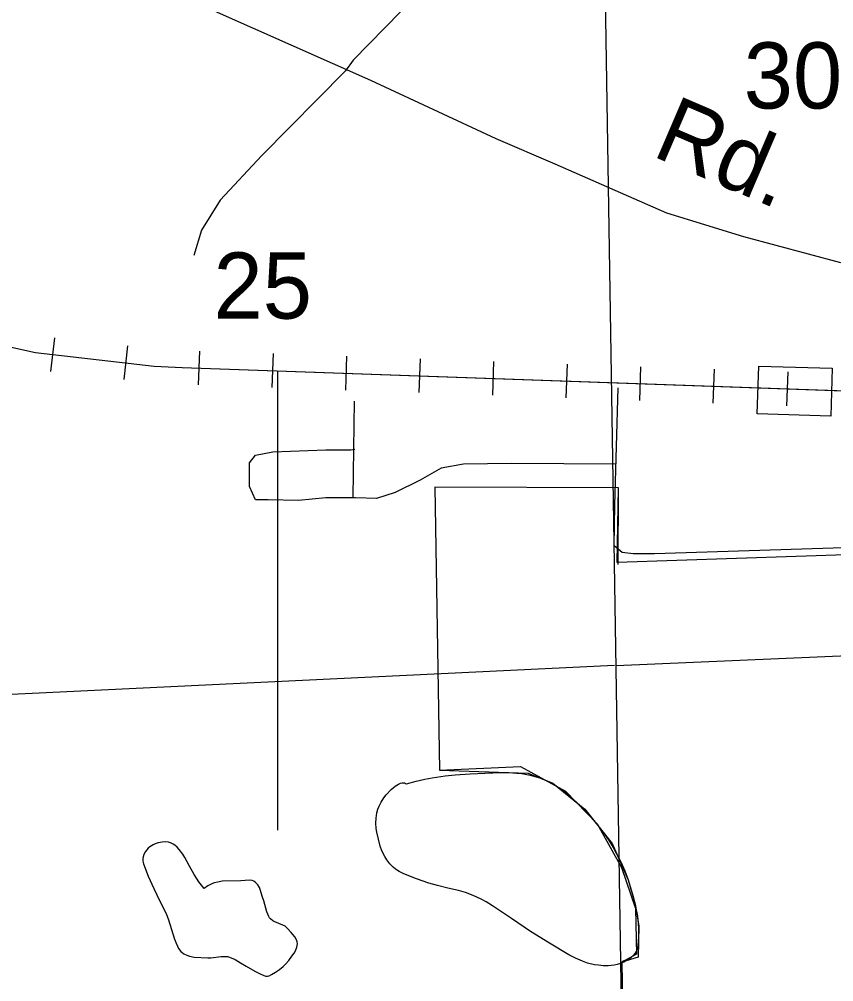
# Model space of a CAD drawing. Extents: x 2480962 to 2688785, y 277103 to 599240.
# Drawn here: x 2545675 to 2551211, y 436042 to 442588 of the extents above; entities that cross this region are included whole.
import ezdxf

# ---------------------------------------------------------------- set-up
doc = ezdxf.new("R2010")
doc.units = 0
for name, color, linetype in [('Cities Incorporated Area', 7, 'Continuous'), ('County Roads Related Text', 7, 'Continuous'), ('County Routes Highway Center Lines', 7, 'Continuous'), ('Lakes and Ponds', 7, 'Continuous'), ('Local Roads Paved', 7, 'Continuous'), ('Railroad Stations', 7, 'Continuous'), ('Railroads', 7, 'Continuous'), ('Section Lines', 7, 'Continuous'), ('Section Numbers', 7, 'Continuous'), ('Swamps', 7, 'Continuous'), ('Township and Range lines', 7, 'Continuous')]:
    doc.layers.add(name, color=color, linetype=linetype)

msp = doc.modelspace()

# ---------------------------------------------------------------- linework, layer by layer
at = {"layer": 'Cities Incorporated Area'}
for p, q in [((2549747.207, 439399.968), (2548499.333, 439406.541)), ((2548499.333, 439406.541), (2548532.218, 437481.839)), ((2549738.264, 438892.674), (2549747.207, 439399.968)), ((2551810.07, 438964.296), (2549738.264, 438892.674)), ((2548532.218, 437481.839), (2549133.672, 437461.643)), ((2549133.672, 437461.643), (2549300.935, 437392.86)), ((2549300.935, 437392.86), (2549519.357, 437216.601)), ((2549519.357, 437216.601), (2549704.592, 436982.806)), ((2549704.592, 436982.806), (2549813.023, 436736.093)), ((2549813.023, 436736.093), (2549861.036, 436569.212)), ((2549861.036, 436569.212), (2549886.56, 436423.341)), ((2549886.56, 436423.341), (2549882.444, 436209.022)), ((2549882.444, 436209.022), (2549769.717, 436175.05)), ((2549769.717, 436175.05), (2549808.561, 434297.514))]:
    msp.add_line(p, q, dxfattribs=at)
at = {"layer": 'County Routes Highway Center Lines'}
msp.add_lwpolyline([(2551260.127, 440930.131), (2550599.271, 441108.275), (2550076.332, 441269.179), (2549317.785, 441602.48), (2548915.524, 441774.878), (2548065.031, 442171.391), (2546720.333, 442769.035)], dxfattribs=at)
at = {"layer": 'Lakes and Ponds'}
for points in [[(2548306.504, 437387.504), (2548372.6, 437406.235), (2548430.599, 437419.65), (2548481.468, 437429.356), (2548570.738, 437442.402), (2548637.887, 437449.435), (2548738.893, 437456.647), (2548840.203, 437461.199), (2548948.549, 437464.432), (2549002.72, 437464.068), (2549056.815, 437461.122), (2549089.785, 437457.551), (2549146.678, 437447.344), (2549188.625, 437436.126), (2549219.65, 437425.565), (2549265.448, 437406.053), (2549310.304, 437381.87), (2549341.57, 437362.054), (2549392.373, 437325.023), (2549427.861, 437295.345), (2549478.191, 437247.894), (2549526.671, 437197.082), (2549567.808, 437151.396), (2549626.102, 437081.415), (2549653.511, 437044.963), (2549679.634, 437007.041), (2549711.193, 436956.1), (2549732.935, 436917.236), (2549762.914, 436857.577), (2549790.304, 436795.904), (2549813.023, 436736.093), (2549827.632, 436690.788), (2549846.762, 436622.234), (2549863.95, 436553.116), (2549876.504, 436488.065), (2549882.081, 436438.485), (2549884.128, 436401.08), (2549883.804, 436344.957), (2549879.452, 436289.239), (2549874.508, 436265.581), (2549867.853, 436248.623), (2549861.145, 436236.539), (2549848.235, 436219.716), (2549831.793, 436204.817), (2549807.634, 436188.584), (2549784.063, 436176.208), (2549761.269, 436166.978), (2549739.383, 436160.304), (2549718.487, 436155.705), (2549678.57, 436151.124), (2549643.161, 436151.106), (2549612.065, 436153.865), (2549584.941, 436158.211), (2549538.098, 436169.683), (2549503.867, 436181.095), (2549454.723, 436201.896), (2549409.165, 436226.077), (2549278.986, 436303.504), (2549150.497, 436384.492), (2549021.557, 436472.073), (2548891.849, 436558.739), (2548847.668, 436585.238), (2548813.639, 436603.442), (2548761.182, 436627.852), (2548707.055, 436648.521), (2548659.978, 436662.33), (2548588.333, 436678.67), (2548516.923, 436696.086), (2548459.426, 436713.352), (2548374.277, 436742.135), (2548289.85, 436775.328), (2548256.286, 436792.269), (2548233.084, 436807.81), (2548216.799, 436821.144), (2548194.179, 436843.976), (2548173.744, 436870.363), (2548159.528, 436893.035), (2548139.802, 436933.468), (2548128.497, 436964.417), (2548115.527, 437011.819), (2548105.312, 437060.375), (2548101.485, 437084.024), (2548098.803, 437119.776), (2548100.154, 437155.371), (2548105.891, 437190.992), (2548113.204, 437216.869), (2548120.542, 437235.954), (2548134.77, 437264.292), (2548153.166, 437292.565), (2548169.558, 437313.66), (2548203.409, 437349.97), (2548231.007, 437372.988), (2548251.768, 437385.802), (2548266.877, 437392.034), (2548277.738, 437394.438), (2548292.96, 437393.84), (2548299.97, 437391.438), (2548306.504, 437387.504)], [(2546931.936, 436675.539), (2546896.054, 436722.083), (2546863.381, 436770.558), (2546831.455, 436828.316), (2546800.134, 436886.683), (2546785.92, 436909.533), (2546762.007, 436941.433), (2546747.842, 436956.516), (2546731.565, 436971.147), (2546721.91, 436978.078), (2546703.798, 436986.746), (2546689.58, 436990.689), (2546667.998, 436993.147), (2546647.061, 436992.287), (2546619.374, 436987.542), (2546599.016, 436981.116), (2546584.058, 436974.206), (2546562.243, 436959.769), (2546551.662, 436950.444), (2546541.328, 436939.55), (2546532.362, 436927.943), (2546521.31, 436907.056), (2546516.701, 436891.165), (2546515.205, 436879.26), (2546515.947, 436861.638), (2546520.07, 436844.564), (2546551.691, 436759.703), (2546588.529, 436675.661), (2546631.141, 436591.114), (2546672.838, 436506.753), (2546689.444, 436464.212), (2546709.299, 436398.358), (2546730.725, 436332.577), (2546741.338, 436304.408), (2546750.155, 436283.682), (2546758.07, 436268.913), (2546773.268, 436248.836), (2546782.83, 436240.047), (2546793.991, 436232.284), (2546814.038, 436222.161), (2546831.727, 436215.957), (2546862.955, 436209.742), (2546957.736, 436205.839), (2546977.613, 436205.687), (2547047.952, 436213.509), (2547065.382, 436214.498), (2547091.139, 436212.878), (2547103.782, 436210.139), (2547116.231, 436205.782), (2547142.587, 436192.771), (2547179.502, 436170.226), (2547216.536, 436147.694), (2547277.106, 436114.208), (2547307.511, 436098.448), (2547337.966, 436084.323), (2547350.806, 436080.95), (2547362.286, 436081.055), (2547372.467, 436083.147), (2547390.457, 436090.439), (2547417.42, 436107.197), (2547443.685, 436126.504), (2547468.842, 436146.89), (2547485.091, 436162.563), (2547507.043, 436187.728), (2547528.334, 436216.19), (2547542.521, 436236.99), (2547551.996, 436252.99), (2547562.316, 436277.087), (2547564.951, 436288.97), (2547565.428, 436300.616), (2547563.081, 436314.469), (2547558.838, 436326.436), (2547547.408, 436347.032), (2547523.719, 436377.102), (2547496.885, 436406.189), (2547481.842, 436419.079), (2547467.035, 436427.821), (2547411.765, 436450.65), (2547399.111, 436456.99), (2547382.59, 436468.971), (2547375.792, 436476.524), (2547370.192, 436485.396), (2547356.996, 436517.372), (2547343.196, 436567.506), (2547336.406, 436592.667), (2547328.1, 436617.347), (2547312.215, 436669.425), (2547307.222, 436682.086), (2547296.655, 436700.41), (2547289.465, 436709.18), (2547280.683, 436717.634), (2547268.766, 436725.855), (2547258.05, 436730.377), (2547238.826, 436733.607), (2547180.316, 436728.226), (2547054.898, 436725.216), (2547023.801, 436720.352), (2547000.61, 436714.025), (2546983.304, 436707.41), (2546957.509, 436693.942), (2546931.936, 436675.539)]]:
    msp.add_lwpolyline(points, dxfattribs=at)
at = {"layer": 'Local Roads Paved'}
msp.add_line((2547950.434, 439989.519), (2547941.251, 439337.571), dxfattribs=at)
for points in [[(2553849.789, 443531.353), (2553552.551, 443339.8), (2552944.863, 442930.271), (2552607.993, 442732.112), (2552224.886, 442613.217), (2551960.674, 442593.401), (2551788.936, 442593.401), (2551399.224, 442626.428), (2550884.01, 442745.323), (2550269.718, 442890.64), (2549675.241, 443029.351), (2549378.003, 443029.351), (2549014.711, 442976.508), (2548631.604, 442851.008), (2548268.313, 442639.638), (2547944.653, 442309.373), (2547891.811, 442236.715), (2547323.755, 441662.054), (2547039.727, 441358.211), (2546914.227, 441153.446), (2546861.384, 440981.709)], [(2551279.038, 438993.233), (2549993.508, 438951.912), (2549846.59, 438951.912), (2549773.132, 438961.095), (2549718.037, 439007.006), (2549722.629, 439282.477), (2549745.585, 440081.342)], [(2549731.811, 439562.539), (2549020.178, 439567.13), (2548694.205, 439562.539), (2548542.696, 439534.992), (2548400.369, 439452.351), (2548230.496, 439369.709), (2548101.943, 439328.389), (2547959.616, 439332.98), (2547757.604, 439332.98), (2547573.957, 439314.615), (2547367.354, 439319.206), (2547280.122, 439319.206), (2547238.801, 439411.03), (2547238.801, 439571.721), (2547280.122, 439622.224), (2547399.492, 439645.18), (2547757.604, 439658.954), (2547927.478, 439658.954), (2547955.025, 439663.545)]]:
    msp.add_lwpolyline(points, dxfattribs=at)
at = {"layer": 'Railroad Stations'}
msp.add_lwpolyline([(2550700.841, 440228.646), (2551200.629, 440214.108), (2551191.179, 439889.245), (2550691.391, 439903.784)], close=True, dxfattribs=at)
at = {"layer": 'Railroads'}
for p, q in [((2545913.627, 440421.644), (2545887.875, 440193.09)), ((2545913.627, 440421.644), (2545887.875, 440193.09)), ((2546410.483, 440365.661), (2546384.731, 440137.108)), ((2546410.483, 440365.661), (2546384.731, 440137.108)), ((2546900.162, 440331.316), (2546892.018, 440101.461)), ((2546900.162, 440331.316), (2546892.018, 440101.461)), ((2547399.849, 440313.61), (2547391.704, 440083.755)), ((2547399.849, 440313.61), (2547391.704, 440083.755)), ((2547899.535, 440295.904), (2547891.39, 440066.049)), ((2547899.535, 440295.904), (2547891.39, 440066.049)), ((2548399.222, 440278.198), (2548391.077, 440048.343)), ((2548399.222, 440278.198), (2548391.077, 440048.343)), ((2548898.908, 440260.492), (2548890.763, 440030.636)), ((2548898.908, 440260.492), (2548890.763, 440030.636)), ((2546781.298, 440220.456), (2557380.702, 439844.874)), ((2549398.594, 440242.786), (2549390.45, 440012.93)), ((2549398.594, 440242.786), (2549390.45, 440012.93)), ((2549898.281, 440225.08), (2549890.136, 439995.224)), ((2549898.281, 440225.08), (2549890.136, 439995.224)), ((2550397.967, 440207.374), (2550389.822, 439977.518)), ((2550397.967, 440207.374), (2550389.822, 439977.518)), ((2550897.654, 440189.668), (2550889.509, 439959.812)), ((2550897.654, 440189.668), (2550889.509, 439959.812))]:
    msp.add_line(p, q, dxfattribs=at)
for points in [[(2504457.222, 450568.165), (2520855.254, 448452.084), (2521247.687, 448380.391), (2521630.476, 448268.069), (2521999.426, 448116.348), (2522298.814, 447957.824), (2522298.813, 447957.824), (2525353.968, 446161.924), (2526001.076, 445825.806), (2526679.773, 445559.173), (2527030.858, 445452.248), (2544991.828, 440495.215), (2545784.966, 440320.413), (2546592.032, 440229.478), (2546781.298, 440220.456), (2557380.702, 439844.874), (2557380.701, 439844.874), (2557789.911, 439808.861), (2557931.671, 439786.211), (2566903.276, 438184.008)], [(2504457.222, 450568.165), (2520855.254, 448452.084), (2521247.687, 448380.391), (2521630.476, 448268.069), (2521999.426, 448116.348), (2522298.814, 447957.824), (2522298.813, 447957.824), (2525353.968, 446161.924), (2526001.076, 445825.806), (2526679.773, 445559.173), (2527030.858, 445452.248), (2544991.828, 440495.215), (2545784.966, 440320.413), (2546592.032, 440229.478), (2546781.298, 440220.456), (2557380.702, 439844.874), (2557380.701, 439844.874), (2557789.911, 439808.861), (2557931.671, 439786.211), (2566903.276, 438184.008)], [(2544991.828, 440495.215), (2545784.966, 440320.413), (2546592.032, 440229.478), (2546781.298, 440220.456)]]:
    msp.add_lwpolyline(points, dxfattribs=at)
at = {"layer": 'Section Lines'}
for p, q in [((2555575.201, 438442.713), (2549731.053, 438190.453)), ((2545043.898, 437969.917), (2549721.164, 438194.103))]:
    msp.add_line(p, q, dxfattribs=at)
at = {"layer": 'Swamps'}
for p, q in [((2547431.459, 437072.726), (2547431.424, 440191.25)), ((2549745.596, 438879.069), (2549747.207, 439399.968))]:
    msp.add_line(p, q, dxfattribs=at)
for points in [[(2547431.426, 439965.237), (2547431.424, 440191.25)], [(2549746.755, 439254.072), (2549747.142, 439379.074)], [(2549746.369, 439129.071), (2549746.755, 439254.072)], [(2548532.218, 437481.839), (2549082.475, 437505.205), (2549387.957, 437338.985), (2549602.075, 437117.112), (2549767.583, 436819.131), (2549863.389, 436541.121), (2549869.351, 436228.706), (2549769.717, 436175.05)], [(2548306.504, 437387.504), (2548372.6, 437406.235), (2548430.599, 437419.65), (2548481.468, 437429.356), (2548570.738, 437442.402), (2548637.887, 437449.435), (2548738.893, 437456.647), (2548840.203, 437461.199), (2548948.549, 437464.432), (2549002.72, 437464.068), (2549056.815, 437461.122), (2549089.785, 437457.551), (2549146.678, 437447.344), (2549188.625, 437436.126), (2549219.65, 437425.565), (2549265.448, 437406.053), (2549310.304, 437381.87), (2549341.57, 437362.054), (2549392.373, 437325.023), (2549427.861, 437295.345), (2549478.191, 437247.894), (2549526.671, 437197.082), (2549567.808, 437151.396), (2549626.102, 437081.415), (2549653.511, 437044.963), (2549679.634, 437007.041), (2549711.193, 436956.1), (2549732.935, 436917.236), (2549762.914, 436857.577), (2549790.304, 436795.904), (2549813.023, 436736.093), (2549827.632, 436690.788), (2549846.762, 436622.234), (2549863.95, 436553.116), (2549876.504, 436488.065), (2549882.081, 436438.485), (2549884.128, 436401.08), (2549883.804, 436344.957), (2549879.452, 436289.239), (2549874.508, 436265.581), (2549867.853, 436248.623), (2549861.145, 436236.539), (2549848.235, 436219.716), (2549831.793, 436204.817), (2549807.634, 436188.584), (2549784.063, 436176.208), (2549761.269, 436166.978), (2549739.383, 436160.304), (2549718.487, 436155.705), (2549678.57, 436151.124), (2549643.161, 436151.106), (2549612.065, 436153.865), (2549584.941, 436158.211), (2549538.098, 436169.683), (2549503.867, 436181.095), (2549454.723, 436201.896), (2549409.165, 436226.077), (2549278.986, 436303.504), (2549150.497, 436384.492), (2549021.557, 436472.073), (2548891.849, 436558.739), (2548847.668, 436585.238), (2548813.639, 436603.442), (2548761.182, 436627.852), (2548707.055, 436648.521), (2548659.978, 436662.33), (2548588.333, 436678.67), (2548516.923, 436696.086), (2548459.426, 436713.352), (2548374.277, 436742.135), (2548289.85, 436775.328), (2548256.286, 436792.269), (2548233.084, 436807.81), (2548216.799, 436821.144), (2548194.179, 436843.976), (2548173.744, 436870.363), (2548159.528, 436893.035), (2548139.802, 436933.468), (2548128.497, 436964.417), (2548115.527, 437011.819), (2548105.312, 437060.375), (2548101.485, 437084.024), (2548098.803, 437119.776), (2548100.154, 437155.371), (2548105.891, 437190.992), (2548113.204, 437216.869), (2548120.542, 437235.954), (2548134.77, 437264.292), (2548153.166, 437292.565), (2548169.558, 437313.66), (2548203.409, 437349.97), (2548231.007, 437372.988), (2548251.768, 437385.802), (2548266.877, 437392.034), (2548277.738, 437394.438), (2548292.96, 437393.84), (2548299.97, 437391.438), (2548306.504, 437387.504)], [(2549785.048, 436183.307), (2549769.717, 436175.05)]]:
    msp.add_lwpolyline(points, dxfattribs=at)
at = {"layer": 'Township and Range lines'}
msp.add_line((2549900.084, 427607.169), (2549561.738, 448791.453), dxfattribs=at)

# ---------------------------------------------------------------- texts
at = {"layer": 'County Roads Related Text'}
msp.add_text('Rd.', height=450, rotation=336.802075, dxfattribs=at).set_placement((2549965.458, 441662.33))
at = {"layer": 'Section Numbers'}
for s, rotation, p in [('30', 359.9992222, (2550599.035, 441980.565)), ('25', 359.9795972, (2546995.091, 440551.752))]:
    msp.add_text(s, height=450, rotation=rotation, dxfattribs=at).set_placement(p)

doc.saveas('drawing.dxf')
